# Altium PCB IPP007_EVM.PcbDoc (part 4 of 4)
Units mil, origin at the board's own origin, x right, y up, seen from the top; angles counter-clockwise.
Board outline 3500.95 x 3103 mil, 6 copper layers (Top Layer, Int1 (GND), Int2 (Sign), Int3 (Sign), Int4 (GND), Bottom Layer), stack 61.068 mil thick; 257 components, 132 nets, 1052 pads, 535 vias.
Unrouted connection lines stored in the file: 3.
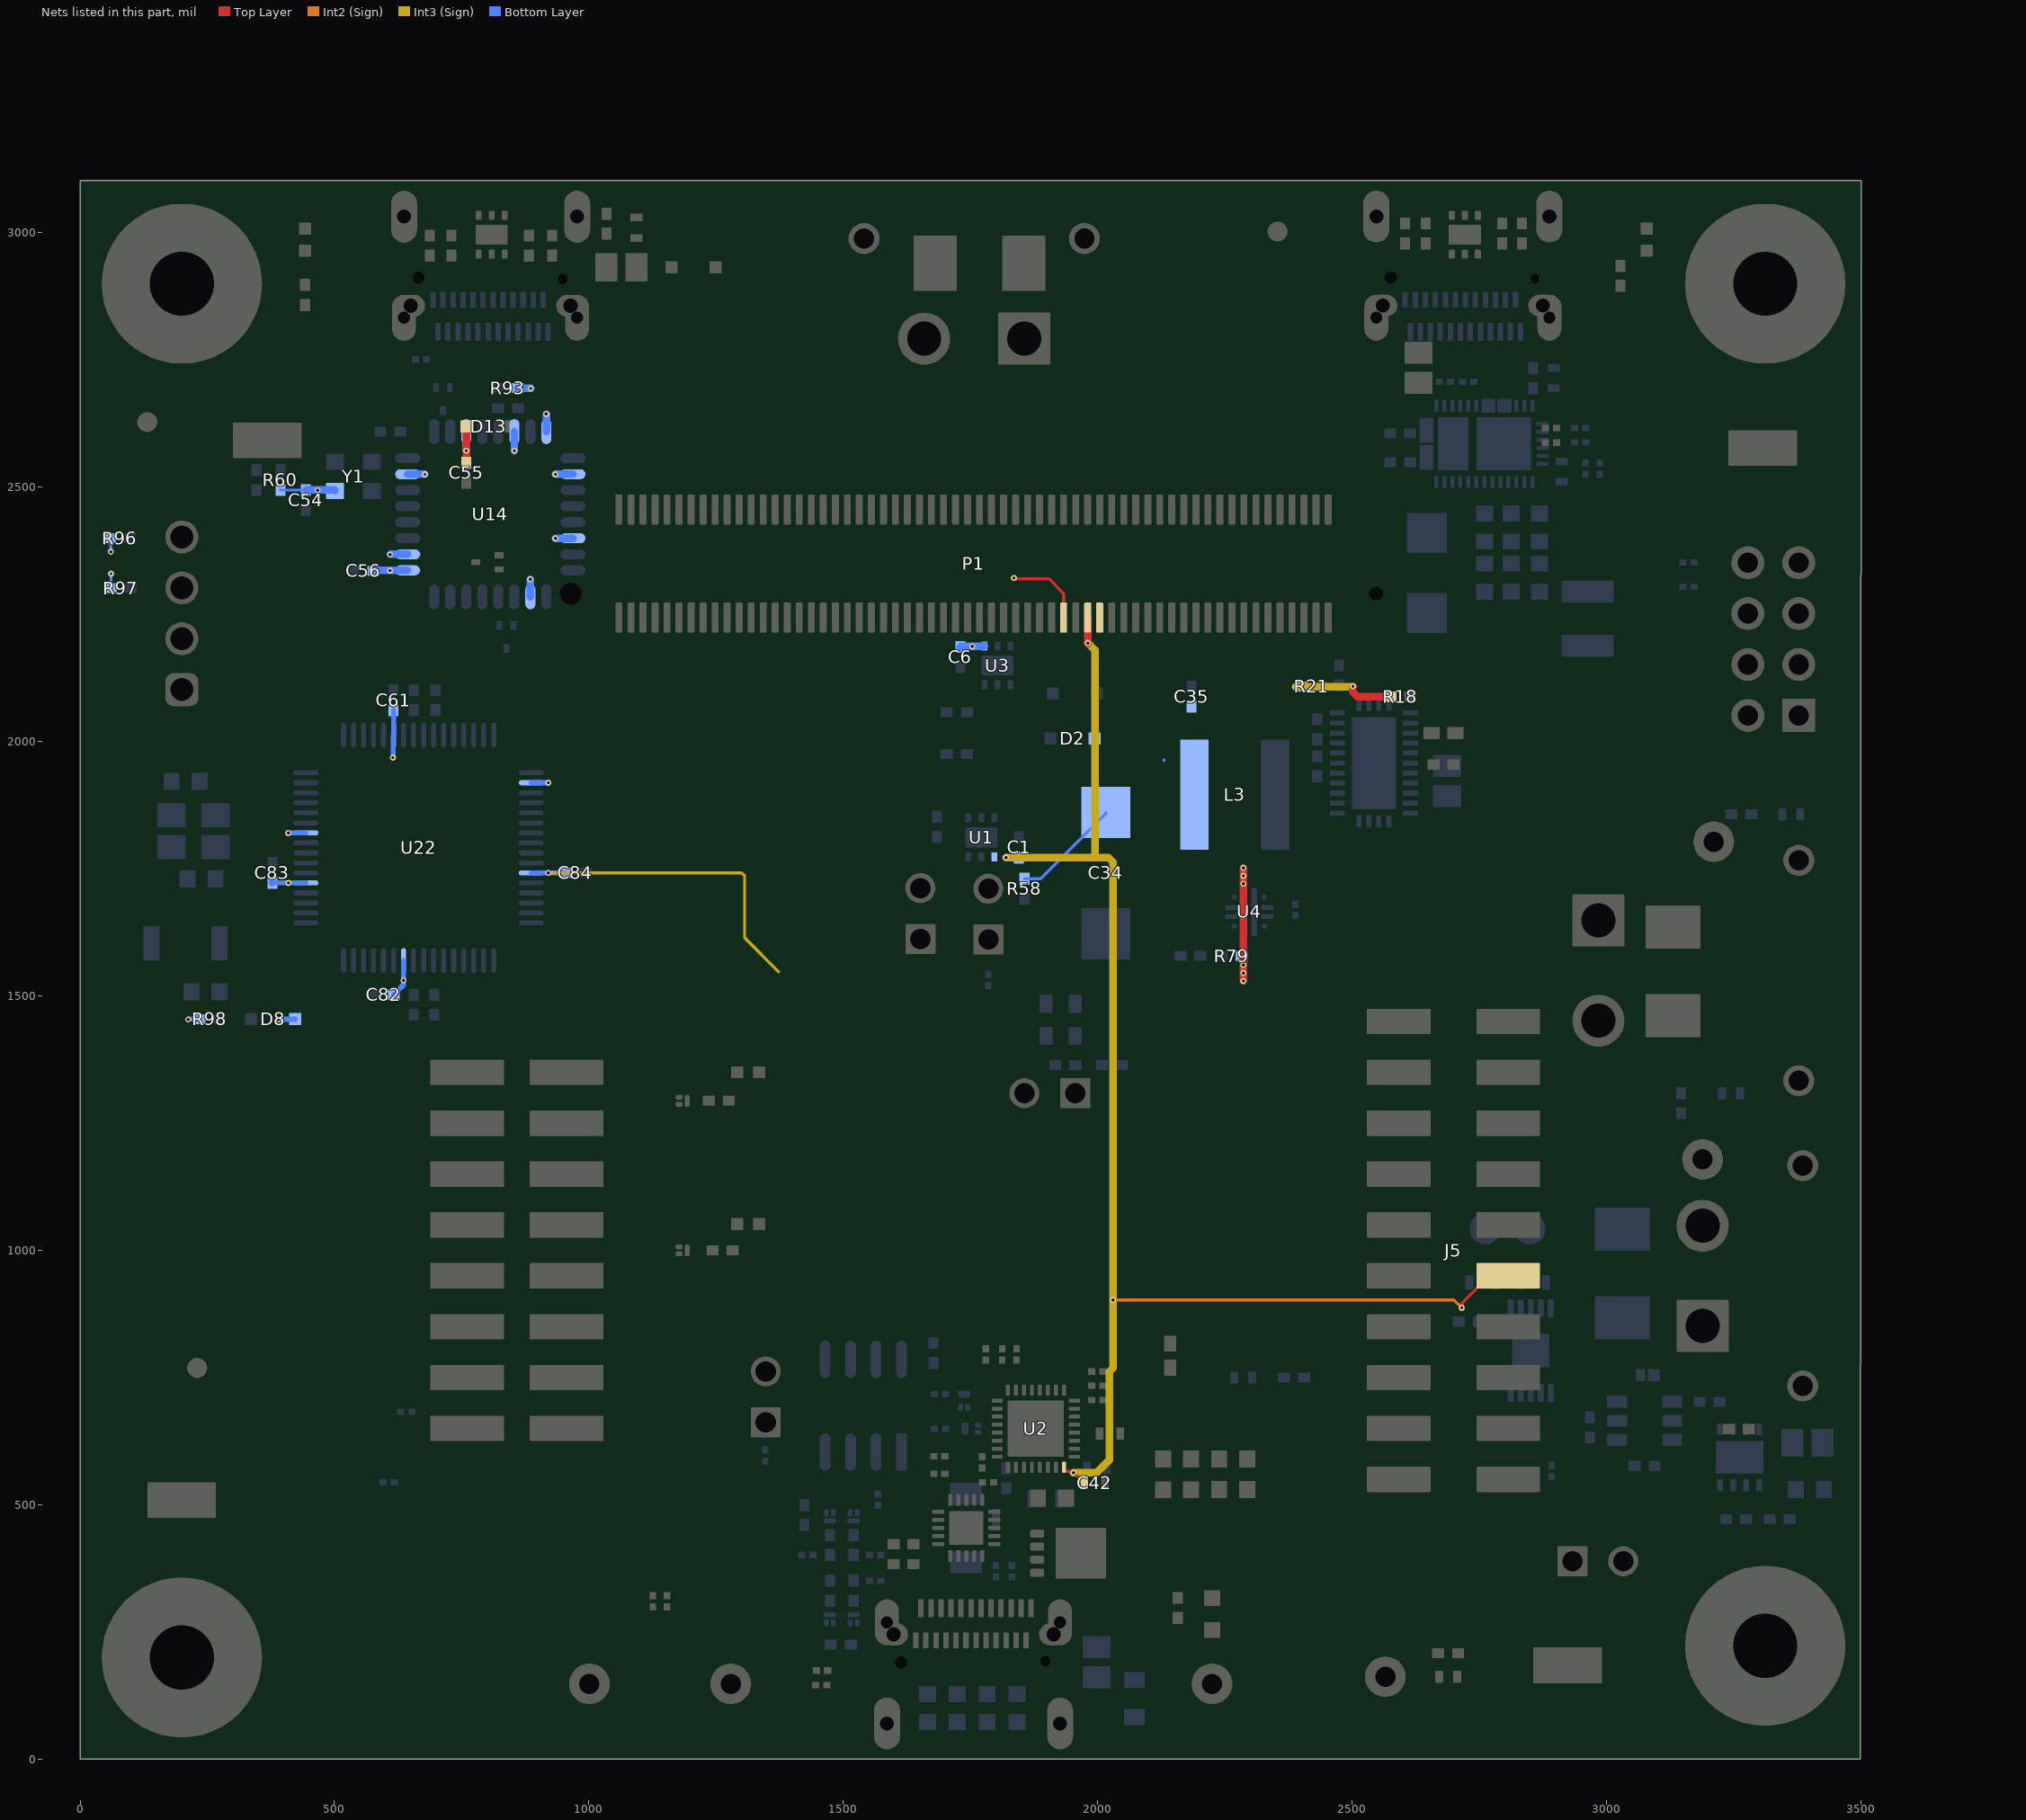
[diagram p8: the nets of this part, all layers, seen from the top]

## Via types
v1: diameter 12, hole 6, Top Layer to Bottom Layer, tented both sides, 471 vias
v2: diameter 19.68, hole 7.87, Top Layer to Bottom Layer, tented both sides, 34 vias
v3: diameter 23.62, hole 11.81, Top Layer to Bottom Layer, 24 vias
v4: diameter 19.68, hole 7.87, Top Layer to Bottom Layer, 6 vias

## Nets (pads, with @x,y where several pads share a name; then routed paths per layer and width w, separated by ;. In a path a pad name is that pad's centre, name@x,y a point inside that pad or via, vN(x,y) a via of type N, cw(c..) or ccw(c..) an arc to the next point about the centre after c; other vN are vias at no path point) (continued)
VCC3V3: C6.1 C54.1 C55.1 C56.1 C61.1 C82.1 C83.1 C84.1 D8.1 D13.1 P1.75 R60.2 R93.2 R96.2 R97.2 R98.1 U3.1 U14.3 U14.6 U14.8 U14.10 U14.14 U14.18 U14.25 U14.26 U14.31 U22.2 U22.11 U22.26 U22.37 U22.42 U22.54 Y1.4 | length 1850.7
  Top Layer w6: v1(1835.34,2321.85) 1837.58,2319.61 1904.41,2319.61 1933.21,2290.8 P1.75@1933.21,2243.7
  Top Layer w15: C55.1@759.11,2548.01 v1(759.11,2571.73) 759.11,2617.54 D13.1@761.31,2619.74
  Int3 (Sign) w6: v1(920.48,1741.97) 1300.72,1741.97 1306.1,1736.58 1306.1,1614.34 1373.11,1547.34
  Bottom Layer w6: R96.2@58.44,2399.68 60.32,2397.81 v1(60.32,2373.2) ; R97.2@60.32,2301.62 60.87,2302.17 v1(60.87,2330.1) ; R60.2@393.84,2494.59 393.98,2494.46 C54.1@443.86,2494.46 ; v1(614.88,1968.61) v1@615.53,1969.26 ; U22.54@615.53,2011.99 U22.54@616.19,2012.64 ; v1(759.11,2571.73) v1@759.5,2571.34
  Bottom Layer w10: v1(212.41,1453.7) 213.27,1454.56 R98.1@234.78,1454.56 ; C83.1@378,1722.31 U22.37@443.93,1722.3 ; v1(389.6,1454.02) 389.88,1454.29 422.39,1454.29 D8.1@422.66,1454.56 ; v1(409.36,1820.36) 409.63,1820.63 443.86,1820.63 U22.42@443.94,1820.71 ; v1@615.53,1969.26 U22.54@615.53,2011.99 ; U22.54@616.19,2012.64 C61.1@616.19,2061.81 ; C82.1@616.34,1502.47 618.31,1502.47 623.15,1507.31 623.15,1509.28 635.87,1522 U22.26@635.87,1569.73 ; U14.31@643.96,2525.67 U14.31@644.11,2525.51 ; v1@677.69,2525.51 v1(677.85,2525.35) ; U22.11@886.85,1741.97 v1(920.48,1741.97) C84.1@954.11,1741.97 ; U22.2@886.85,1919.14 v1(920.48,1919.14)
  Bottom Layer w15: C54.1@443.86,2494.59 500.91,2494.59 Y1.4@500.91,2492.77 ; C56.1@577.87,2336.69 U14.25@643.96,2336.69 ; v1@609.72,2368.19 U14.26@643.96,2368.19 ; U14.31@644.11,2525.51 v1@677.69,2525.51 ; v1(759.11,2571.73) U14.3@759.11,2609.33 U14.3@760.01,2610.22 ; v1(853.6,2571.73) U14.6@853.6,2609.33 ; R93.2@860.19,2694.75 885.33,2694.75 v1(885.87,2694.21) ; U14.18@885.1,2284.52 v1@885.1,2318.76 ; U14.8@916.59,2609.33 v1@916.59,2643.56 ; v1@934.53,2399.68 U14.14@968.76,2399.68 ; v1@934.53,2525.67 U14.10@968.76,2525.67 ; C6.1@1729.95,2185.92 1731.07,2187.04 v1(1753.75,2187.04) 1776.42,2187.04 U3.1@1777.55,2188.16
  other v1: 635.87,1530.84 409.39,1722.06 884.72,2319.14 609.34,2336.31 609.34,2367.8 934.14,2399.3 467.09,2494.06 934.14,2525.28 916.21,2643.94
VCC5V: C34.1 C35.1 D2.2 L3.2 R18.2 R21.2 R58.2 R79.2 U4.5 | length 638.1
  Top Layer w15: v1(2286.29,1529.51) v1@2286.36,1751.12 ; v1(2501.72,2108.77) 2501.72,2097.12 2510.5,2088.33 R18.2@2575.34,2088.33
  Int3 (Sign) w15: v1(2389.46,2108.1) 2389.6,2108.24 2501.18,2108.24 v1@2501.31,2108.36
  Bottom Layer w6: R58.2@1856.12,1730.62 1887.81,1730.62 2015.89,1858.7 C34.1@2015.89,1860.67 ; 2129.88,1963.55 2130.49,1962.94
  other v1: 2286.44,1545.1 2286.58,1560.68 2286.42,1720.73 2286.57,1736.32 2286.71,1751.9
VDDIO: P1.81
VIN_3V3: C1.1 C42.1 J5.B06 P1.79 U1.1 U2.32 | length 2824.6
  Top Layer w6: U2.32@1933.71,573.8 1933.71,567.03 1934.64,566.09 1948.69,566.09 1949.84,564.94 1950.29,564.94 v1(1952.24,562.99) 1972.46,542.77 C42.1@1974.43,542.77 ; v1(2715.63,887.14) 2716.78,888.29 2716.78,897.41 2769.36,950 J5.B06@2806.96,950
  Top Layer w15: P1.79@1980.45,2243.7 1980.45,2192.86 1980.46,2193.39 v1(1980.84,2193.78)
  Int2 (Sign) w6: v1(2030.19,902.65) 2700.12,902.65 v1(2715.63,887.14)
  Int3 (Sign) w15: v1(1819.93,1772.28) 1994.61,1772.28 ; v1(1952.24,562.99) 1998.03,562.99 2023.02,587.99 2023.02,761.52 2030.07,768.57 2030.07,828.39 ; v1(1980.84,2193.78) 1994.61,2180.01 1994.61,1772.28 ; 2030.04,828.41 2030.04,1763.49 2021.25,1772.28 1994.61,1772.28
pads on no net: FID1.1 FID2.1 FID3.1 H5.0 H6.0 H7.0 H8.0 J3.A2 J3.A3 J3.A6 J3.A7 J3.A8 J3.A10 J3.A11 J3.ALIGN1 J3.ALIGN2 J3.B2 J3.B3 J3.B6 J3.B7 J3.B8 J3.B10 J3.B11 J4.A2 J4.A3 J4.A10 J4.A11 J4.ALIGN1 J4.ALIGN2 J4.B2 J4.B3 J4.B10 J4.B11 J6.A2 J6.A3 J6.A8 J6.A10 J6.A11 J6.ALIGN1 J6.ALIGN2 J6.B2 J6.B3 J6.B8 J6.B10 J6.B11 LBL1.0 P1. P1.3 P1.5 P1.7 P1.9 P1.13 P1.15 P1.17 P1.19 P1.23 P1.25 P1.34 P1.36 P1.39 P1.40 P1.41 P1.42 P1.43 P1.44 P1.46 P1.50 P1.52 P1.54 P1.55 P1.56 P1.57 P1.58 P1.59 P1.62 P1.63 P1.64 P1.65 P1.66 P1.67 P1.68 P1.71 P1.72 P1.73 P1.74 P1.76 P1.78 P1.82 P1.84 P1.86 P1.88 P1.92 P1.94 P1.95 P1.96 P1.97 P1.98 P1.102 P1.104 P1.106 P1.108 P1.112 P1.114 P1.116 P1.118 Q8.9A Q8.9B Q8.9C Q8.9D Q15.1@1177.31,1007.87 Q15.2@1177.31,992.13 Q18.1@1177.31,1301.98 Q18.2@1177.31,1286.24 QN1.1@1465.81,484.04 QN1.2@1481.55,484.04 QN2.1@1512.45,484.04 QN2.2@1528.2,484.04 QP1.1@1481.55,268 QP1.2@1465.81,268 QP2.1@1528.2,267.99 QP2.2@1512.45,267.99 SH-J11.0 SH-J12.0 SH-J13.0 SH-J14.0 SH-J15.0 U1.2 U1.5 U1.7@1753.65,1812.01 U1.7@1789.09,1812.01 U2.21 U3.2 U3.5 U3.7@1785.42,2149.77 U3.7@1820.85,2149.77 U4.3 U4.4 U4.7 U4.10 U7.5 U7.6 U7.7 U7.10 U7.13 U7.18 U7.19 U7.26 U7.27 U7.36 U7.37 U8.7@2703.94,2996.38 U8.7@2739.37,2996.38 U9.10 U9.11 U9.31A U10.10 U14.5 U14.9 U14.13 U14.17 U14.29 U14.32 U17.7@791.06,2996.38 U17.7@826.49,2996.38 U20.3 U20.6 U20.7 U20.9@3236.87,593.38 U20.9@3286.47,593.38 U22.1 U22.4 U22.5 U22.6 U22.7 U22.8 U22.9 U22.10 U22.14 U22.15 U22.16 U22.18 U22.19 U22.20 U22.21 U22.28 U22.29 U22.30 U22.31 U22.33 U22.36 U22.45 U22.46 U22.53 U22.57 U22.58 U22.59 U22.60 U22.61 U22.62 U22.63 U22.64

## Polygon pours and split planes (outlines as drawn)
RP_VBUS on Top Layer "TOP_LAYER_RP_VBUS_P134" (solid, pour order 134): 910.19,2881.25 1059.67,2881.25 1059.67,3014.06 1012.71,3014.23 1012.92,2967.38 677.01,2967.38 677.01,2765.86 910.19,2765.86
RP_5V on Top Layer "TOP_LAYER_RP_5V_P175" (solid, pour order 175): 1066.16,3014.06 1066.16,2881.25 1143.31,2881.25 1174.32,2912.26 1174.32,2951.68 1111.94,3014.06
730_VBUS on Top Layer "TOP_LAYER_730_VBUS_P076" (solid, pour order 76): 2594.37,2990.86 2594.37,2967.26 2594.37,2742.76 2800.76,2742.76 2838.23,2780.23 2838.23,2961.93 2843.53,2967.23 2843.53,2990.86 2785.21,2990.86 2761.59,2967.23 2678.18,2967.23 2654.56,2990.86
730_VBUS_C on Top Layer "TOP_LAYER_730_VBUS_C_P078" (solid, pour order 78): 2781.77,2709.3 2781.77,2645.73 2648.54,2645.73 2648.54,2614.01 2597.8,2613.84 2597.8,2709.3
NetU7_15 on Top Layer "TOP_LAYER_NETU7_15_P083" (solid, pour order 83): 2743.31,2658.43 2743.31,2509.71 2644.58,2509.71 2644.58,2619.04 2683.97,2658.43
GND on Top Layer "TOP_LAYER_GND_P181" (solid, remove dead copper, pour order 181): 0,0 3499.34,0 3500.95,3103 0,3103
HV_VSYS on Top Layer "TOP_LAYER_HV_VSYS_P173" (solid, pour order 173): 1590.27,2729.04 1743.29,2729.04 1743.29,3004.58 1590.27,3004.58
HV_VSYS on Top Layer "TOP_LAYER_HV_VSYS_P166" (solid, pour order 166): 2935.12,1538.02 2935.12,1388.39 3221.85,1388.39 3221.85,1538.02
PPHV on Top Layer "TOP_LAYER_PPHV_P145" (solid, pour order 145): 3128.15,954.96 3278.15,954.96 3278.15,1226.24 3128.15,1226.24
VBUS_LV on Top Layer "TOP_LAYER_VBUS_LV_P088" (solid, pour order 88): 1823.16,585.83 1831.53,379.98 1911.55,379.98 1911.55,479.87 1858.9,497.99 1858.9,585.83
PP5V on Top Layer "TOP_LAYER_PP5V_P087" (solid, pour order 87): 1864.62,587.34 1892.28,587.34 1892.28,496.93 1864.62,496.93
VBUS_LV on Bottom Layer "BOTTOM_LAYER_VBUS_LV_P199" (solid, pour order 199): 1876.63,468.67 1810.4,468.67 1810.4,557.72 1878.69,557.72
NetC33_1 on Bottom Layer "BOTTOM_LAYER_NETC33_1_P160" (solid, pour order 160): 2311.47,2003.57 2376.28,2003.57 2422.47,1944.29 2487.47,1944.29 2487.47,1849.75 2460.95,1849.75 2399.59,1788.38 2311.47,1788.38
VBUS_C on Bottom Layer "BOTTOM_LAYER_VBUS_C_P161" (solid, pour order 161): 1816.15,183 2092.83,183 2092.83,106.31 1974.25,106.31 1648.73,106.31 1648.73,143.81 1682.01,144.52 1682.01,323.99 1729.55,323.99 1804.35,323.99 1816.15,323.99
730_VBUS_C on Bottom Layer "BOTTOM_LAYER_730_VBUS_C_P103" (solid, pour order 103): 2658.15,2589.36 2601.29,2589.36 2601.29,2665.98 2658.15,2665.98
730_VBUS_C on Bottom Layer "BOTTOM_LAYER_730_VBUS_C_P153" (solid, pour order 153): 2754.11,2647.3 2781.77,2647.3 2781.77,2701.31 2754.11,2701.31
GND on Bottom Layer "BOTTOM_LAYER_GND_P202" (solid, remove dead copper, pour order 202): 18.52,33.02 3517.86,33.02 3519.47,3136.02 18.51,3136.02
PPHV on Bottom Layer "BOTTOM_LAYER_PPHV_P195" (solid, pour order 195): 3286.2,636.6 3334.18,636.5 3334.21,594.76 3377.51,594.76 3377.51,678.59 3341.67,714.44 3341.67,1086.98 3190.57,1086.98 3179.35,1075.76 3179.35,998.63 3179.94,998.04 3248.13,998.04 3273.01,973.16 3273.01,636.6
NetQ3_1 on Bottom Layer "BOTTOM_LAYER_NETQ3_1_P187" (solid, pour order 187): 2889.65,883.83 2889.65,963.75 2745.97,963.75 2745.97,883.83
PPHV on Bottom Layer "BOTTOM_LAYER_PPHV_P193" (solid, pour order 193): 3249.19,996.15 2815.03,996.15 2815.03,1281.44 3249.19,1281.44
VBUS on Bottom Layer "Bottom Layer-VBUS" (solid, pour order 191): 1889.4,382.42 1963.45,308.37 1963.45,106.31 2456.27,106.31 2718.48,396.19 2718.48,1005.1 2805.98,1004.79 2806.92,1196.28 2386.53,1196.28 2386.53,639.48 2066.71,461.45 1889.4,461.45
HV_VSYS on Bottom Layer "Bottom Layer-HV_VSYS" (solid, pour order 189): 2802.84,1706.09 2933.07,1706.09 2933.07,1399.42 3260.97,1399.42 3260.97,1944.29 3260.97,1962.86 2970.95,2252.87 2835.76,2252.87 2013.07,3075.57 1606.44,3075.57 1606.44,2652.19 2011.52,2652.19 2650.65,2060.12 2650.01,1988.65 2587.99,1988.27 2588.19,1923.06 2802.84,1922.84
PP5V on Bottom Layer "Bottom Layer-PP5V" (solid, remove dead copper, pour order 80): 2321.95,1609.48 2323.77,1611.3 2316.45,1618.61 2315.46,1618.61 2315.46,1712.54 2315.59,1712.54 2321.09,1718.04 2321.09,1757.87 2315.46,1757.87 2315.46,1757.89 2312.16,1757.87 2303.29,1757.87 2303.29,1757.81 2301.96,1757.8 2301.96,1572.27 2321.95,1572.27
VIN_3V3 on Bottom Layer "BOTTOM_LAYER_VIN_3V3_P178" (solid, pour order 178): 1790.58,1786.67 1790.55,1786.64 1790.55,1760.47 1870.6,1760.47 1870.6,1786.67
NetC2_1 on Bottom Layer "BOTTOM_LAYER_NETC2_1_P186" (solid, pour order 186): 1779.1,1834.65 1924.3,1834.65 1924.3,2109.42 1907.94,2125.79 1771.45,2125.79 1731.09,2085.42 1731.09,1949.35 1774.01,1906.42 1774.01,1890.72 1779.1,1885.63
VCC5V on Bottom Layer "BOTTOM_LAYER_VCC5V_P093" (solid, pour order 93): 2413.08,2121.92 2288.39,2121.92 2242.99,2076.52 1932.22,2076.52 1932.22,1773 2266.98,1773 2266.98,1581.95 2266.98,1522.77 2301.96,1522.77 2301.96,1990.29 2413.08,2101.41
GND on Bottom Layer "BOTTOM_LAYER_GND_P119" (solid, pour order 119): 2826.81,2552.47 2758.74,2552.47 2758.74,2629.09 2826.81,2629.09
TC_VSYS on Bottom Layer "BOTTOM_LAYER_TC_VSYS_P162" (solid, pour order 162): 2659.72,2580.72 2601.29,2580.72 2601.29,2370.74 2643.04,2329 2886.78,2329 2886.78,2408.97 2738.79,2408.97 2659.72,2488.03
PP5V on Bottom Layer "BOTTOM_LAYER_PP5V_P089" (solid, pour order 89): 1864.62,563.28 1892.28,563.28 1892.28,493.74 1864.62,493.74
HV_VSYS on Int3 (Sign) "Bottom Layer-HV_VSYS" (solid, remove dead copper, pour order 165): 2881.57,1538.46 2881.57,1395.24 3314.28,1395.24 3314.28,2949.28 2139.36,2949.28 1605.72,2949.28 1585.19,2949.28 1585.19,2707.8 1726.95,2707.8
LDO_3V3 on Int3 (Sign) "INT3_(SIGN)_LDO_3V3_P197" (solid, pour order 197): 0,0 3499.35,0 3500.95,3103 0,3103
VCC3V3 on Int3 (Sign) "INT3_(SIGN)_VCC3V3_P172" (solid, remove dead copper, pour order 172): 0,2701.31 0,1433.79 925.74,1433.79 1860.9,1433.79 1860.9,2701.31 622.55,2701.31
PP5V on Int3 (Sign) "INT3_(SIGN)_PP5V_P171" (solid, pour order 171): 1864.62,563.28 1864.62,483.2 1882.73,465.09 2222.86,465.09 2407.95,650.18 2407.81,1757.8 2022.83,1757.8 2022.83,661.05 2022.83,567.94 1997.03,542.14 1893.09,542.14 1893.09,563.28
PP5V on Int2 (Sign) "Bottom Layer-PP5V" (solid, pour order 176): 2325.68,1757.9 2302.62,1757.85 2301.96,1572.27 2325.68,1572.27
GND on Int2 (Sign) "INT2_(SIGN)_GND_P198" (solid, pour order 198): -1.85,-2 3497.5,-2 3499.1,3101 -1.85,3101
VCC5V on Int2 (Sign) "INT2_(SIGN)_VCC5V_P196" (solid, pour order 196): 2265.07,1514.94 2265.07,1760.47 2294.08,1760.47 2294.08,1514.94
GND on Int1 (GND) "INT1_(GND)_GND_P200" (solid, pour order 200): 0,0 3499.35,0 3500.95,3103 0,3103
GND on Int4 (GND) "INT4_(GND)_GND_P201" (solid, pour order 201): 0,0 3499.35,0 3500.95,3103 0,3103

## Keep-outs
Keep-Out Layer:
  text ".Layer_Name" at -1042.12,-1285.47 h60

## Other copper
Top Layer:
  text ".Layer_Name" at -1042.12,-1285.47 h60
Bottom Layer:
  text ".Layer_Name" at -1042.12,-1285.47 h60

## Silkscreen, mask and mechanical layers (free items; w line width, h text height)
Top Overlay:
  lines w8: 1047.71,1287.22 1119.1,1287.22
  lines w10: 1425.74,-4.06 1424.86,898.67 2077.52,896.02 2078.65,-4.06
  text "Data" at 415.9,2930.53 h60 r90
  text "Power" at 3166.59,2803.28 h60 r90
  text "GND" at 3261.78,2642.37 h60
  text "HV_SYS" at 1579.86,2611.5 h100
  text "GND" at 310.22,2470.8 h60
  text "VIN3V3 EN" at 1662.24,1798.52 h60 r90
  text "PP5V_EN" at 1799.06,1798.46 h60 r90
  text "I2Cc_SCL" at 2854.48,1508.51 h60 r90
  text "I2Cc_SDA" at 2577.74,1497.47 h60 r90
  text "HV_SYS" at 3450.99,1382.38 h100 r90
  text "I2Ct_IRQ" at 437.51,1335.79 h60
  text "PP_EN" at 1042.36,1334.38 h60
  text "ADCIN2" at 2304.22,1330.62 h60
  text "ADCIN1" at 2885.34,1330.8 h60
  text "I2Ct_SCL" at 428.46,1235.79 h60
  text "FLT" at 1042.36,1230.8 h60
  text "SBU2" at 2363.15,1230.8 h60
  text "SBU1" at 2885.34,1230.8 h60
  text "I2Ct_SDA" at 420.58,1135.79 h60
  text "GPIO1" at 1042.36,1130.8 h60
  text "GND" at 2378.16,1130.8 h60
  text "GND" at 2885.34,1130.8 h60
  text "I2Cc_IRQ" at 425.58,1035.79 h60
  text "GPIO2" at 1042.36,1030.8 h60
  text "Populated: Safe Mode / Removed: Always Enable Sink" at 1522.49,1031.07 h60
  text "CC2" at 2389.87,1030.8 h60
  text "CC1" at 2885.34,1030.8 h60
  text "LDO_3V3" at 2268.75,935.97 h60
  text "VIN_3V3" at 2885.4,936.04 h60
  text "GND" at 540.74,930.8 h60
  text "GND" at 1042.36,930.8 h60
  text "EPR Implementation" at 1420.91,927.16 h80
  text "PPHV" at 3454.79,835.8 h100 r90
  text "PP5V" at 2365.43,834.69 h60
  text "GPIO11" at 473.08,830.8 h60
  text "GPIO3" at 1042.36,830.8 h60
  text "HV_VSYS / D10" at 2882.33,797.59 h60
  text "VBUS_D10" at 2226.4,735.97 h60
  text "GPIO7" at 495.51,730.8 h60
  text "GPIO4" at 1042.36,730.8 h60
  text "PPHV_D10" at 2884.51,707.3 h60
  text "VBUS_LV_D10" at 2133.88,635.79 h60
  text "GPIO6" at 495.51,630.8 h60
  text "GPIO5" at 1042.36,630.8 h60
  text "GND" at 145.84,567.35 h60
  text "GND" at 2387.52,530.8 h60
  text "GND" at 2885.34,528.85 h60
  text "PPHV System Reg Dis" at 2317.45,373.36 h60
  text "EEPROM ENABLE" at 1401.7,288.45 h60 r90
  text ".PRJ_Number" at 458,253.28 h60
  text "Rev .SCH_Rev" at 457.64,199.28 h60
  text "GND" at 2870.11,59.58 h60
  text "VBUS_LV" at 2447.54,49.79 h60
  text "VBUS" at 2153.36,44.8 h60
  text "C_CC2" at 915.78,35.59 h60
  text "C_CC1" at 1197.2,35.59 h60
  text ".Layer_Name" at -1042.12,-1285.47 h60
Bottom Overlay:
  text ".Layer_Name" at -1042.12,-1285.47 h60
Top Paste:
  text ".Layer_Name" at -1042.12,-1285.47 h60
Bottom Paste:
  text ".Layer_Name" at -1042.12,-1285.47 h60
Top Solder:
  text ".Layer_Name" at -1042.12,-1285.47 h60
  text ".Layer_Name" at -1042.12,-1285.47 h60
Bottom Solder:
  text ".Layer_Name" at -1042.12,-1285.47 h60
Drill Guide:
  text ".Layer_Name" at -1042.12,-1285.47 h60
M1 Board Outline:
  lines w5: 3500,3101 3500,0 0,0 0,3103 3500,3103
  text ".Layer_Name" at -1042.12,-1285.47 h60
M2 Board Dimensions:
  rectangle: -1619.12,-701.97 -1494.12,-576.97
  rectangle: -1494.12,-826.97 -1119.12,-701.97
  lines w7: -1619.12,-701.97 -619.12,-701.97 ; -1494.12,-826.97 -1494.12,-576.97 ; -1369.12,-826.97 -1369.12,-576.97 ; -1119.12,-826.97 -1119.12,-576.97 ; -869.12,-826.97 -869.12,-576.97 ; -1619.12,-826.97 -619.12,-826.97 -619.12,-576.97 -1619.12,-576.97 -1619.12,-826.97
  text ".Layer_Name" at -1042.12,-1285.47 h60
M3 3D STEP Top:
  text ".Layer_Name" at -1042.12,-1285.47 h60
M4 3D STEP Bottom:
  text ".Layer_Name" at -1042.12,-1285.47 h60
M5 Assembly Top:
  lines w10: -1911.12,-1357.14 4688.88,-1357.14 ; -1911.12,-1153.81 4690.88,-1153.81 ; -1911.12,-950.47 -1911.12,-1560.47 2093.88,-1560.47 4690.88,-1560.47 4690.88,-950.47 -1910.62,-950.47 -1910.62,-1560.47 -335.12,-1560.47 ; 553.88,-1560.47 553.88,-950.47 ; 1820.88,-1153.81 1820.88,-950.47 ; 2660.88,-1153.81 2660.88,-950.47 ; 3282.88,-1566.97 3282.88,-1364.14
  text "COMPONENTS MARKED 'DNP' SHOULD NOT BE POPULATED." at -465.62,-745.47 h60
  text "ASSEMBLY VARIANT:" at -466.12,-860.97 h60
  text ".VariantName" at 569.88,-860.97 h60
  text "PCB VIEWED FROM TOP SIDE" at -1847.62,-1082.64 h60
  text "BOARD #:" at 628.88,-1082.64 h60
  text ".PRJ_Number" at 1174.38,-1082.64 h60
  text "REV:" at 2018.88,-1082.64 h60
  text ".PCB_Rev" at 2310.38,-1082.64 h60
  text "SVN REV:" at 2856.88,-1082.64 h60
  text ".VersionControl_RevNumber" at 3362.88,-1082.64 h60
  text "TID #:" at 628.88,-1285.97 h60
  text ".TID" at 1174.38,-1285.97 h60
  text "PLOT NAME =" at -1847.62,-1491.31 h60
  text ".plot_File_Name" at -1042.12,-1491.31 h60
  text "GENERATED    :" at 630.88,-1491.31 h60
  text ".Print_Date" at 1500.38,-1491.31 h60
  text ".Print_Time" at 2229.38,-1491.31 h60
  text "TEXAS INSTRUMENTS" at 3493.88,-1491.31 h60
M6 Assembly Bottom:
  lines w10: -1911.62,-1154.31 4690.38,-1154.31 ; -1909.62,-1357.64 4690.38,-1357.64 ; -503.62,-1567.47 -503.62,-1364.64 ; 118.38,-1154.31 118.38,-950.97 ; 958.38,-1154.31 958.38,-950.97 ; 2225.38,-1560.97 2225.38,-950.97 ; 3114.38,-1560.97 4689.88,-1560.97 4689.88,-950.97 -1911.62,-950.97 -1911.62,-1560.97 685.38,-1560.97 4690.38,-1560.97 4690.38,-950.97
  text "COMPONENTS MARKED 'DNP' SHOULD NOT BE POPULATED." at 4482.88,-744.97 h60
  text ".VariantName" at 3438.88,-860.97 h60
  text "ASSEMBLY VARIANT:" at 4477.88,-860.97 h60
  text ".VersionControl_RevNumber" at -583.62,-1083.14 h60
  text "SVN REV:" at -77.62,-1083.14 h60
  text ".PCB_Rev" at 468.88,-1083.14 h60
  text "REV:" at 760.38,-1083.14 h60
  text ".PRJ_Number" at 1604.88,-1083.14 h60
  text "BOARD #:" at 2150.38,-1083.14 h60
  text "PCB VIEWED FROM BOTTOM SIDE" at 4626.88,-1083.14 h60
  text ".TID" at 1604.88,-1286.47 h60
  text "TID #:" at 2150.38,-1286.47 h60
  text "TEXAS INSTRUMENTS" at -714.62,-1491.81 h60
  text ".Print_Time" at 549.88,-1491.81 h60
  text ".Print_Date" at 1278.88,-1491.81 h60
  text "GENERATED    :" at 2148.38,-1491.81 h60
  text ".plot_File_Name" at 3821.38,-1491.81 h60
  text "PLOT NAME =" at 4626.88,-1491.81 h60
M9 Title Sheet:
  drawing of 57 lines, arcs and shapes, not listed
  text "1" at -879.29,7609.53 h70
  text "2" at 1616.38,7609.53 h70
  text "3" at 4105.72,7609.53 h70
  text "4" at 6612.39,7609.53 h70
  text "5" at 9111.38,7609.53 h70
  text "6" at 11616.38,7609.53 h70
  text "A" at -2035.62,6466.53 h70
  text "A" at 12764.38,6466.53 h70
  text "B" at -2035.62,4086.53 h70
  text "B" at 12764.38,4086.53 h70
  text "C" at -2035.62,1711.53 h70
  text "C" at 12764.38,1711.53 h70
  text "PROJECT TITLE:" at 9724.38,-149.47 h45
  text ".PRJ_Title" at 9774.38,-282.8 h70
  text "DESIGNED FOR:" at 9724.38,-450.47 h45
  text ".PRJ_Customer" at 9774.38,-590.47 h70
  text "D" at -2035.62,-658.47 h70
  text "D" at 12764.38,-658.47 h70
  text "FILE NAME:" at 9724.38,-750.47 h45
  text ".PCB_File_Name_No_Path" at 9774.38,-870.47 h70
  text "Texas Instruments (TI) and/or its licensors do not warrant the accuracy or completeness of this specification" at 4754.88,-1032.31 h45
  text "ENGINEER:" at 9724.38,-1040.47 h45
  text "LAYOUT BY:" at 11229.38,-1040.47 h45
  text "or any information contained therein. TI and/or its licensors do not warrant that this design will meet" at 4709.89,-1144.98 h45
  text ".PRJ_Engineer" at 9774.38,-1195.46 h70
  text ".PCB_Layout" at 11279.88,-1195.46 h70
  text "the specifications, will be suitable for your application or fit for any particular purpose, or will operate in" at 4709.89,-1257.64 h45
  text ".Layer_Name" at -1042.12,-1285.47 h60
  text "ALTIUM DESIGNER VERSION:" at 11229.38,-1350.47 h45
  text "an implementation. TI and/or its licensors do not warrant that the design is production worthy. You should" at 4709.89,-1370.31 h45
  text "completely validate and test your design implementation to confirm the system functionality for your application." at 4754.88,-1482.97 h45
  text ".print_Scale" at 9774.38,-1483.8 h70
  text ".Application_BuildNumber" at 11279.88,-1483.8 h70
  text "1" at -879.29,-1690.47 h70
  text "2" at 1616.38,-1690.47 h70
  text "3" at 4105.72,-1690.47 h70
  text "4" at 6612.39,-1690.47 h70
  text "5" at 9111.38,-1690.47 h70
  text "6" at 11616.38,-1690.47 h70
M10 Fab Notes:
  drawing of 189 lines, arcs and shapes, not listed
  text "DESIGN INFORMATION" at 10762.89,5929.2 h60
  text "MIN. TRACK WIDTH:" at 10118.33,5797.08 h60
  text "6" at 11214.58,5797.08 h60
  text "MIL" at 11369.33,5797.08 h60
  text "4" at 11218,5690 h60
  text "MIN. CLEARANCE:" at 10118.33,5672.95 h60
  text "MIL" at 11369.33,5672.95 h60
  text "MIN. VIA PAD SIZE:" at 10118.33,5548.82 h60
  text "12" at 11184.59,5548.83 h60
  text "MIL" at 11369.33,5548.82 h60
  text "0.05mm (2MIL)" at 10813.34,5418.92 h60
  text "MINIMUM ANNULAR RING" at 9789.1,5410.7 h60
  text "EXTERNAL" at 11521.34,5410.7 h60
  text "PER" at 9989.1,5300.58 h60
  text "IPC-D-275 CLASS 2 LEVEL C" at 10209.1,5300.57 h60
  text "MIL, HOLES" at 11697.33,5200.1 h60
  text "+/-" at 11304.88,5191.51 h60
  text "+/-" at 12158.88,5191.51 h60
  text "REGISTRATION TOLERANCES:" at 9789.1,5190.45 h60
  text "METAL" at 10988.88,5190.45 h60
  text "5" at 11565.08,5190.45 h60
  text "3" at 12398.08,5190.45 h60
  text "MIL" at 12514.33,5190.45 h60
  text "HOLE SIZE TOLERANCE (UNLESS OTHERWISE SPECIFIED):" at 9789.1,5092.13 h60
  text "+/-" at 12158.88,5089.26 h60
  text "3" at 12398.08,5088.2 h60
  text "MIL" at 12514.33,5088.19 h60
  text "MATERIAL:" at 9714.34,4950.55 h60
  text "FR-4 High Tg" at 10700.78,4822.02 h60
  text "X" at 10556.34,4814.03 h60
  text "FR-408" at 10135.34,4809.52 h60
  text "OTHER" at 11623.34,4809.52 h60
  text "62 MIL (1.6mm) +/-10%" at 10455.44,4666.49 h60
  text "X" at 10335.34,4664.03 h60
  text "THICKNESS:" at 9789.1,4658.27 h60
  text "OTHER" at 11740.34,4658.27 h60
  text "TOLERANCE:" at 9789.1,4519.95 h60
  text "X" at 10637.34,4519.95 h60
  text "ANSI IPC-6012 TYPE 3 CLASS 2" at 10815.35,4519.95 h60
  text "OTHER +/-" at 10815.34,4375.76 h60
  text "BOW & TWIST:" at 9789.1,4230.57 h60
  text "X" at 10637.34,4230.57 h60
  text "ANSI IPC-6012 TYPE 3 CLASS 2" at 10815.35,4230.57 h60
  text "OTHER +/-" at 10815.34,4083.88 h60
  text "DRILLING:" at 9714.34,3953.26 h60
  text "NC_DRILL FILES" at 11475.33,3848.07 h60
  text "REFERENCE:" at 9789.1,3844.13 h60
  text "X" at 10446.34,3844.03 h60
  text "AS SHOWN" at 10624.33,3844.13 h60
  text "X" at 11347.34,3844.13 h60
  text "OTHER" at 11773.34,3701.88 h60
  text "PTH COPPER THICKNESS:" at 9788.78,3698.35 h60
  text "X" at 10928.02,3698.35 h60
  text "20-30 um" at 11056.01,3698.35 h60
  text "BOARD FINISH:" at 9714.34,3550.75 h60
  text "SILKSCREEN:" at 9869.56,3440.63 h60
  text "X" at 10827.34,3440.63 h60
  text "TOP" at 10944.33,3440.63 h60
  text "X" at 11337.34,3440.63 h60
  text "BOTTOM" at 11455.33,3440.63 h60
  text "SILKSCREEN COLOR:" at 9869.56,3285.44 h60
  text "X" at 10826.34,3285.44 h60
  text "WHITE" at 10944.33,3285.44 h60
  text "OTHER" at 11455.33,3285.44 h60
  text "X" at 11557.09,3158.44 h60
  text "Red" at 12039.37,3152.53 h60
  text "GREEN" at 11075.33,3141.99 h60
  text "OTHER" at 11693.34,3141.99 h60
  text "SOLDER RESIST COLOR:" at 9869.56,3135.12 h60
  text "X" at 10957.34,2987.74 h60
  text "MATTE" at 11075.33,2987.74 h60
  text "SEMI-GLOSS" at 11692.88,2987.1 h60
  text "IMMERSION GOLD (ENIG)" at 10775.33,2814.97 h60
  text "ENEPIG" at 12112.88,2807.75 h60
  text "SURFACE FINISH:" at 9714.34,2806.75 h60
  text "X" at 10597.34,2806.75 h60
  text "IMM. TIN/SILVER OR EQUIV" at 10043.88,2669.43 h60
  text "OTHER" at 11475.34,2665.49 h60
  text "ARRAY/PANEL:" at 9714.34,2510.12 h60
  text "CUT AND TRIM PER M1 BOARD OUTLINE" at 10775.34,2501.89 h60
  text "N.C. ROUTE" at 10775.33,2365.93 h60
  text "X" at 11463.34,2365.93 h60
  text "V. SCORE" at 11641.34,2365.93 h60
  text "CERTIFICATION:" at 9714.34,2236.8 h60
  text "MATERIALS AND WORKMANSHIP FOR ALL PCBS" at 10439.34,2236.8 h60
  text "TO MEET OR EXCEED THE REQUIREMENTS OF:" at 10439.34,2142.74 h60
  text "X" at 10076.84,2014.11 h60
  text "ANSI IPC-A-600F CLASS ->" at 10204.84,2014.11 h60
  text "X" at 11852.84,2014.11 h60
  text "2" at 11962.84,2014.11 h60
  text "1" at 11647.84,2012.61 h60
  text "3" at 12316.84,2012.61 h60
  text "X" at 10888.84,1866.42 h60
  text "RoHS" at 11016.84,1866.42 h60
  text "OTHER" at 11661.24,1866.42 h60
  text "PER ORDER" at 12058.3,1866.42 h60
  text "ALL BOARDS MUST MEET OR EXCEED UL94-V0 REQUIREMENTS." at 9741.88,1712.6 h60
  text "PCB MUST BEAR THE UL94V-0 UL REGISTERED MATERIAL ID NUMBER" at 9741.88,1596.53 h60
  text "ADDITIONAL REQUIREMENTS:" at 9714.34,1427.11 h60
  text "MICROSECTION:" at 9789.1,1319.98 h60
  text "YES" at 10694.84,1319.98 h60
  text "REQUIRED" at 11556.33,1175.65 h60
  text "BARE BOARD ELEC. TEST:" at 9789.1,1172.79 h60
  text "NONE" at 11094.84,1172.79 h60
  text "X" at 11438.34,1172.79 h60
  text "PER ORDER" at 12148.34,1172.79 h60
  text "XX MIL VIAS REQUIRE NON-CONDUCTIVE FILL AND PLANARIZE" at 9957.25,967.85 h59
  text "XX MIL VIAS REQUIRE CONDUCTIVE FILL AND PLANARIZE" at 9965.25,863.87 h60
  text "OUTER XX MIL TRACES REQUIRE 50 OHM SINGLE-ENDED IMPEDANCE" at 9964.27,700.49 h58
  text "LAYER 2 & 3 (INNER LAYERS) XX MIL WIDE, XX MIL SPACE / TRACES REQUIRE 100 OHM DIFFERENTIAL IMPEDANCE" at 9956.27,464.77 h60
  text ".Layer_Name" at -1042.12,-1285.47 h60
M11 Gerber Information:
  lines w10: -1911.12,-1357.14 4688.88,-1357.14 ; -1911.12,-1153.81 4690.88,-1153.81 ; -1911.12,-950.47 -1911.12,-1560.47 2093.88,-1560.47 4690.88,-1560.47 4690.88,-950.47 -1910.62,-950.47 -1910.62,-1560.47 -335.12,-1560.47 ; 553.88,-1560.47 553.88,-950.47 ; 1820.88,-1153.81 1820.88,-950.47 ; 2660.88,-1153.81 2660.88,-950.47 ; 3282.88,-1566.97 3282.88,-1364.14
  text "ALL ARTWORK VIEWED FROM TOP SIDE" at -1847.62,-1082.64 h60
  text "BOARD #:" at 628.88,-1082.64 h60
  text ".PRJ_Number" at 1174.38,-1082.64 h60
  text "REV:" at 2018.88,-1082.64 h60
  text ".PCB_Rev" at 2310.38,-1082.64 h60
  text "SVN REV:" at 2856.88,-1082.64 h60
  text ".VersionControl_RevNumber" at 3362.88,-1082.64 h60
  text "LAYER NAME =" at -1847.62,-1285.47 h60
  text "TID #:" at 628.88,-1285.97 h60
  text ".TID" at 1174.38,-1285.97 h60
  text "PLOT NAME =" at -1847.62,-1491.31 h60
  text ".plot_File_Name" at -1042.12,-1491.31 h60
  text "GENERATED    :" at 630.88,-1491.31 h60
  text ".Print_Date" at 1500.38,-1491.31 h60
  text ".Print_Time" at 2229.38,-1491.31 h60
  text "TEXAS INSTRUMENTS" at 3493.88,-1491.31 h60
M12 Stackup:
  drawing of 349 lines, arcs and shapes, not listed
  text "Layer" at 4055.9,7253.63 h60
  text "Name" at 4306.99,7253.63 h60
  text "Material" at 4947.58,7253.63 h60
  text "Thickness" at 5286.53,7253.63 h60
  text "Constant" at 5644.95,7253.63 h60
  text "Board Layer Stack" at 5976.69,7253.63 h60
  text "Top Overlay" at 4306.99,7133.63 h60
  text "Top Solder" at 4306.99,7013.63 h60
  text "SM-001" at 4947.58,7013.63 h60
  text "1.00mil" at 5286.53,7013.63 h60
  text "4" at 5644.95,7013.63 h60
  text "Top Surface Finish" at 4306.99,6893.63 h60
  text "PbSn" at 4947.58,6893.63 h60
  text "0.79mil" at 5286.53,6893.63 h60
  text "1" at 4055.9,6773.63 h60
  text "Top Layer" at 4306.99,6773.63 h60
  text "CF-004" at 4947.58,6773.63 h60
  text "1.38mil" at 5286.53,6773.63 h60
  text "Dielectric 1" at 4306.99,6653.63 h60
  text "PP-006" at 4947.58,6653.63 h60
  text "2.80mil" at 5286.47,6653.63 h60
  text "4.1" at 5644.95,6653.63 h60
  text "Dielectric 2" at 4306.99,6533.63 h60
  text "PP-006" at 4947.58,6533.63 h60
  text "2.80mil" at 5286.47,6533.63 h60
  text "4.1" at 5644.95,6533.63 h60
  text "2" at 4055.84,6413.63 h60
  text "Int1 (GND)" at 4306.99,6413.63 h60
  text "CF-004" at 4947.58,6413.63 h60
  text "1.38mil" at 5286.53,6413.63 h60
  text "Dielectric 3" at 4306.99,6293.63 h60
  text "Core-035" at 4947.58,6293.63 h60
  text "18.00mil" at 5286.53,6293.63 h60
  text "4.7" at 5644.95,6293.63 h60
  text "3" at 4055.9,6173.63 h60
  text "Int2 (Sign)" at 4306.99,6173.63 h60
  text "CF-004" at 4947.58,6173.63 h60
  text "1.38mil" at 5286.53,6173.63 h60
  text "Dielectric 4" at 4306.99,6053.63 h60
  text "PP-006" at 4947.58,6053.63 h60
  text "2.80mil" at 5286.47,6053.63 h60
  text "4.1" at 5644.95,6053.63 h60
  text "Dielectric 5" at 4306.99,5933.63 h60
  text "PP-006" at 4947.58,5933.63 h60
  text "2.80mil" at 5286.47,5933.63 h60
  text "4.1" at 5644.95,5933.63 h60
  text "4" at 4055.9,5813.63 h60
  text "Int3 (Sign)" at 4306.99,5813.63 h60
  text "CF-004" at 4947.58,5813.63 h60
  text "1.38mil" at 5286.53,5813.63 h60
  text "Dielectric 6" at 4306.99,5693.63 h60
  text "Core-035" at 4947.58,5693.63 h60
  text "18.00mil" at 5286.53,5693.63 h60
  text "4.7" at 5644.95,5693.63 h60
  text "5" at 4055.9,5573.63 h60
  text "Int4 (GND)" at 4306.99,5573.63 h60
  text "CF-004" at 4947.58,5573.63 h60
  text "1.38mil" at 5286.53,5573.63 h60
  text "Dielectric 7" at 4306.99,5453.63 h60
  text "PP-006" at 4947.58,5453.63 h60
  text "2.80mil" at 5286.47,5453.63 h60
  text "4.1" at 5644.95,5453.63 h60
  text "Dielectric 8" at 4306.99,5333.63 h60
  text "PP-006" at 4947.58,5333.63 h60
  text "2.80mil" at 5286.47,5333.63 h60
  text "4.1" at 5644.95,5333.63 h60
  text "6" at 4055.9,5213.63 h60
  text "Bottom Layer" at 4306.99,5213.63 h60
  text "CF-004" at 4947.58,5213.63 h60
  text "1.38mil" at 5286.53,5213.63 h60
  text "Bottom Surface Finish" at 4306.99,5093.63 h60
  text "PbSn" at 4947.58,5093.63 h60
  text "0.79mil" at 5286.53,5093.63 h60
  text "Bottom Solder" at 4306.99,4973.63 h60
  text "SM-001" at 4947.58,4973.63 h60
  text "1.00mil" at 5286.53,4973.63 h60
  text "4" at 5644.95,4973.63 h60
  text "Bottom Overlay" at 4306.99,4853.63 h60
  text ".Layer_Name" at -1042.12,-1285.47 h60
M13 Component Bodies Top:
  text ".Layer_Name" at -1042.12,-1285.47 h60
M14 Component Bodies Bottom:
  text ".Layer_Name" at -1042.12,-1285.47 h60
M15 Courtyards Top:
  text ".Layer_Name" at -1042.12,-1285.47 h60
M16 Courtyards Bottom:
  text ".Layer_Name" at -1042.12,-1285.47 h60
Drill Drawing:
  drawing of 184 lines, arcs and shapes, not listed
  text "Symbol" at 4007.22,4052.52 h72
  text "Quantity" at 4307.78,4052.52 h72
  text "Finished Hole Size" at 4639.78,4052.52 h72
  text "Plated" at 5276.35,4052.52 h72
  text "Hole Type" at 5535.49,4052.52 h72
  text "Drill Layer Pair" at 5910.64,4052.52 h72
  text "Hole Tolerance" at 6634.97,4052.52 h72
  text "3" at 4307.78,3928.2 h60
  text "23.62mil (0.600mm)" at 4639.78,3928.2 h60
  text "NPTH" at 5276.35,3928.2 h60
  text "Round" at 5535.49,3928.2 h60
  text "Top Layer - Bottom Layer" at 5910.64,3928.2 h60
  text "+/-1.18mil" at 6634.97,3928.2 h60
  text "1" at 4307.78,3803.88 h60
  text "27.56mil (0.700mm)" at 4639.78,3803.88 h60
  text "NPTH" at 5276.35,3803.88 h60
  text "Round" at 5535.49,3803.88 h60
  text "Top Layer - Bottom Layer" at 5910.64,3803.88 h60
  text "+1.97mil" at 6634.97,3803.88 h60
  text "1" at 4307.78,3679.56 h60
  text "43.31mil (1.100mm)" at 4639.78,3679.56 h60
  text "NPTH" at 5276.35,3679.56 h60
  text "Round" at 5535.49,3679.56 h60
  text "Top Layer - Bottom Layer" at 5910.64,3679.56 h60
  text "+1.97mil" at 6634.97,3679.56 h60
  text "471" at 4307.78,3555.24 h60
  text "6.00mil (0.152mm)" at 4639.78,3555.24 h60
  text "PTH" at 5276.35,3555.24 h60
  text "Round" at 5535.49,3555.24 h60
  text "Top Layer - Bottom Layer" at 5910.64,3555.24 h60
  text "40" at 4307.78,3430.92 h60
  text "7.87mil (0.200mm)" at 4639.78,3430.92 h60
  text "PTH" at 5276.35,3430.92 h60
  text "Round" at 5535.49,3430.92 h60
  text "Top Layer - Bottom Layer" at 5910.64,3430.92 h60
  text "24" at 4307.78,3306.6 h60
  text "11.81mil (0.300mm)" at 4639.78,3306.6 h60
  text "PTH" at 5276.35,3306.6 h60
  text "Round" at 5535.49,3306.6 h60
  text "Top Layer - Bottom Layer" at 5910.64,3306.6 h60
  text "6" at 4307.78,3182.28 h60
  text "39.37mil (1.000mm)" at 4639.78,3182.28 h60
  text "PTH" at 5276.35,3182.28 h60
  text "Round" at 5535.49,3182.28 h60
  text "Top Layer - Bottom Layer" at 5910.64,3182.28 h60
  text "24" at 4307.78,3057.96 h60
  text "40.00mil (1.016mm)" at 4639.78,3057.96 h60
  text "PTH" at 5276.35,3057.96 h60
  text "Round" at 5535.49,3057.96 h60
  text "Top Layer - Bottom Layer" at 5910.64,3057.96 h60
  text "4" at 4307.78,2933.64 h60
  text "45.28mil (1.150mm)" at 4639.78,2933.64 h60
  text "PTH" at 5276.35,2933.64 h60
  text "Round" at 5535.49,2933.64 h60
  text "Top Layer - Bottom Layer" at 5910.64,2933.64 h60
  text "6" at 4307.78,2809.32 h60
  text "66.93mil (1.700mm)" at 4639.78,2809.32 h60
  text "PTH" at 5276.35,2809.32 h60
  text "Round" at 5535.49,2809.32 h60
  text "Top Layer - Bottom Layer" at 5910.64,2809.32 h60
  text "4" at 4307.78,2685 h60
  text "125.98mil (3.200mm)" at 4639.78,2685 h60
  text "PTH" at 5276.35,2685 h60
  text "Round" at 5535.49,2685 h60
  text "Top Layer - Bottom Layer" at 5910.64,2685 h60
  text "3" at 4307.78,2560.68 h60
  text "19.69mil (0.500mm)" at 4639.78,2560.68 h60
  text "NPTH" at 5276.35,2560.68 h60
  text "Slot" at 5535.49,2560.68 h60
  text "Top Layer - Bottom Layer" at 5910.64,2560.68 h60
  text "+/-1.18mil" at 6634.97,2560.68 h60
  text "6" at 4307.78,2436.36 h60
  text "23.62mil (0.600mm)" at 4639.78,2436.36 h60
  text "PTH" at 5276.35,2436.36 h60
  text "Slot" at 5535.49,2436.36 h60
  text "Top Layer - Bottom Layer" at 5910.64,2436.36 h60
  text "+/-1.97mil" at 6634.97,2436.36 h60
  text "6" at 4307.78,2312.04 h60
  text "27.56mil (0.700mm)" at 4639.78,2312.04 h60
  text "PTH" at 5276.35,2312.04 h60
  text "Slot" at 5535.49,2312.04 h60
  text "Top Layer - Bottom Layer" at 5910.64,2312.04 h60
  text "+/-1.97mil" at 6634.97,2312.04 h60
  text "6" at 4307.78,2187.72 h60
  text "27.56mil (0.700mm)" at 4639.78,2187.72 h60
  text "PTH" at 5276.35,2187.72 h60
  text "Slot" at 5535.49,2187.72 h60
  text "Top Layer - Bottom Layer" at 5910.64,2187.72 h60
  text "+/-1.97mil" at 6634.97,2187.72 h60
  text "605 Total" at 4307.78,2063.4 h60
  text "Slot definitions :" at 4007.22,1976.38 h60
  text "Routed Path Length" at 4457.93,1976.38 h60
  text "= Calculated from tool start centre position to tool end centre position." at 4997.67,1976.38 h60
  text "Hole Length" at 4457.93,1926.65 h60
  text "= Routed Path Length + Tool Size = Slot length as defined in the PCB layout" at 4797.87,1926.65 h60
  text ".Layer_Name" at -1042.12,-1285.47 h60
M17 Embedded Cavity:
  text ".Layer_Name" at -1042.12,-1285.47 h60
M18 Embedded Assembly:
  text ".Layer_Name" at -1042.12,-1285.47 h60
M19 Embedded Keepout:
  text ".Layer_Name" at -1042.12,-1285.47 h60

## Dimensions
0,3103 to 0,0 on M2 Board Dimensions
-12.75,2.16 to 3499.35,0 on M2 Board Dimensions
-1619.12,-826.97 to -619.12,-826.97 on M2 Board Dimensions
